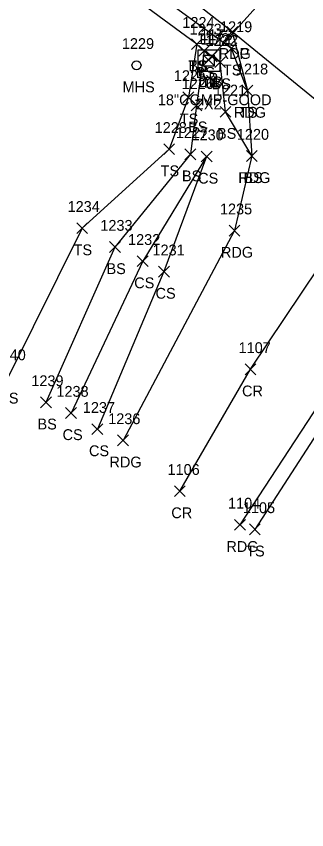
# Model space of a CAD drawing. Extents: x 1537342 to 1542195, y 163002 to 168596.
# Drawn here: x 1541938.8 to 1541992.5, y 163030.1 to 163180.4 of the extents above; entities that cross this region are included whole.
import ezdxf

# ---------------------------------------------------------------- set-up
doc = ezdxf.new("R2010")
doc.units = 0
for name, color, linetype in [('D_A', 7, 'Continuous'), ('D_C', 7, 'Continuous'), ('D_I', 7, 'Continuous'), ('D_TIC', 7, 'Continuous'), ('DCP', 7, 'Continuous'), ('DS', 7, 'Continuous'), ('L_A', 7, 'Continuous'), ('L_I', 7, 'Continuous'), ('L_TIC', 7, 'Continuous'), ('LELB', 7, 'Continuous'), ('P_A', 7, 'Continuous'), ('P_I', 7, 'Continuous'), ('P_TIC', 7, 'Continuous'), ('PET', 7, 'Continuous'), ('PEU', 7, 'Continuous'), ('PRC', 7, 'Continuous'), ('U_A', 7, 'Continuous'), ('U_I', 7, 'Continuous'), ('USMH', 7, 'Continuous')]:
    doc.layers.add(name, color=color, linetype=linetype)

msp = doc.modelspace()

# ---------------------------------------------------------------- linework, layer by layer
at = {"layer": 'D_TIC'}
for points in [[(1541973.36, 163171.23), (1541975.36, 163173.23)], [(1541975.36, 163171.23), (1541973.36, 163173.23)], [(1541973.93, 163171.92), (1541975.93, 163173.92)], [(1541975.93, 163171.92), (1541973.93, 163173.92)]]:
    msp.add_lwpolyline(points, dxfattribs=at)
at = {"layer": 'DCP'}
msp.add_lwpolyline([(1541974.93, 163172.92), (1542058.96, 163266.56)], dxfattribs=at)
at = {"layer": 'DS'}
for p, q in [((1541972.41, 163174.14), (1541976.41, 163174.14)), ((1541972.41, 163170.14), (1541972.41, 163174.14)), ((1541976.41, 163174.14), (1541976.41, 163170.14)), ((1541973.41, 163171.14), (1541973.41, 163173.14)), ((1541973.41, 163173.14), (1541975.41, 163173.14)), ((1541975.41, 163173.14), (1541975.41, 163171.14)), ((1541975.41, 163171.14), (1541973.41, 163171.14)), ((1541974.41, 163172.14), (1541974.41, 163172.14)), ((1541974.41, 163172.14), (1541974.41, 163172.14)), ((1541976.41, 163170.14), (1541972.41, 163170.14))]:
    msp.add_line(p, q, dxfattribs=at)
at = {"layer": 'L_TIC'}
for points in [[(1541971.19, 163174.21), (1541973.19, 163176.21)], [(1541973.19, 163174.21), (1541971.19, 163176.21)], [(1541971.19, 163174.21), (1541973.19, 163176.21)], [(1541973.19, 163174.21), (1541971.19, 163176.21)], [(1541972.52, 163172.98), (1541974.52, 163174.98)], [(1541974.52, 163172.98), (1541972.52, 163174.98)], [(1541972.52, 163172.98), (1541974.52, 163174.98)], [(1541974.52, 163172.98), (1541972.52, 163174.98)], [(1541977.59, 163173.42), (1541979.59, 163175.42)], [(1541979.59, 163173.42), (1541977.59, 163175.42)], [(1541975.49, 163170.88), (1541977.49, 163172.88)], [(1541977.49, 163170.88), (1541975.49, 163172.88)], [(1541980.52, 163165.61), (1541982.52, 163167.61)], [(1541982.52, 163165.61), (1541980.52, 163167.61)], [(1541969.62, 163164.38), (1541971.62, 163166.38)], [(1541971.62, 163164.38), (1541969.62, 163166.38)], [(1541971.12, 163162.91), (1541973.12, 163164.91)], [(1541973.12, 163162.91), (1541971.12, 163164.91)], [(1541976.46, 163161.71), (1541978.46, 163163.71)], [(1541978.46, 163161.71), (1541976.46, 163163.71)], [(1541966.08, 163154.79), (1541968.08, 163156.79)], [(1541968.08, 163154.79), (1541966.08, 163156.79)], [(1541969.99, 163153.86), (1541971.99, 163155.86)], [(1541971.99, 163153.86), (1541969.99, 163155.86)], [(1541972.98, 163153.44), (1541974.98, 163155.44)], [(1541974.98, 163153.44), (1541972.98, 163155.44)], [(1541972.98, 163153.44), (1541974.98, 163155.44)], [(1541974.98, 163153.44), (1541972.98, 163155.44)], [(1541981.35, 163153.54), (1541983.35, 163155.54)], [(1541983.35, 163153.54), (1541981.35, 163155.54)], [(1541950, 163140.2), (1541952, 163142.2)], [(1541952, 163140.2), (1541950, 163142.2)], [(1541956.05, 163136.72), (1541958.05, 163138.72)], [(1541958.05, 163136.72), (1541956.05, 163138.72)], [(1541961.17, 163134.1), (1541963.17, 163136.1)], [(1541963.17, 163134.1), (1541961.17, 163136.1)], [(1541965.11, 163132.17), (1541967.11, 163134.17)], [(1541967.11, 163132.17), (1541965.11, 163134.17)], [(1541943.3, 163108.01), (1541945.3, 163110.01)], [(1541945.3, 163108.01), (1541943.3, 163110.01)], [(1541947.93, 163106.05), (1541949.93, 163108.05)], [(1541949.93, 163106.05), (1541947.93, 163108.05)], [(1541952.8, 163103.07), (1541954.8, 163105.07)], [(1541954.8, 163103.07), (1541952.8, 163105.07)], [(1541981.89, 163084.55), (1541983.89, 163086.55)], [(1541983.89, 163084.55), (1541981.89, 163086.55)]]:
    msp.add_lwpolyline(points, dxfattribs=at)
at = {"layer": 'LELB'}
for points in [[(1541981.52, 163166.61), (1541978.59, 163174.42), (1541956.98, 163190.15), (1541924.16, 163215.18), (1541866.46, 163254), (1541852.65, 163260.98), (1541835.08, 163274.97), (1541811.52, 163294.95), (1541800.6, 163304.36), (1541792.57, 163308.98)], [(1541982.35, 163154.54), (1541977.46, 163162.71), (1541976.49, 163171.88), (1541973.52, 163173.98), (1541972.19, 163175.21), (1541955.89, 163187.24), (1541919.33, 163210.02), (1541893.74, 163229.08), (1541863.64, 163247.96), (1541848.89, 163252.66), (1541830.96, 163271.76), (1541807.53, 163290.35), (1541793.3, 163299.34), (1541792.63, 163303.62)], [(1541972.19, 163175.21), (1541970.62, 163165.38), (1541967.08, 163155.79), (1541951, 163141.2), (1541937.4, 163113.8)], [(1541973.52, 163173.98), (1541972.12, 163163.91), (1541970.99, 163154.86), (1541957.05, 163137.72), (1541944.3, 163109.01)], [(1541973.98, 163154.44), (1541962.17, 163135.1), (1541948.93, 163107.05)], [(1541973.98, 163154.44), (1541966.11, 163133.17), (1541953.8, 163104.07)], [(1542027.61, 163125.22), (1542015.77, 163124.56), (1542008.35, 163121.99), (1541997.1, 163107.53), (1541982.89, 163085.55)]]:
    msp.add_lwpolyline(points, dxfattribs=at)
at = {"layer": 'P_TIC'}
for points in [[(1541977.73, 163176.48), (1541979.73, 163178.48)], [(1541979.73, 163176.48), (1541977.73, 163178.48)], [(1541977.73, 163176.48), (1541979.73, 163178.48)], [(1541979.73, 163176.48), (1541977.73, 163178.48)], [(1541980.52, 163165.61), (1541982.52, 163167.61)], [(1541982.52, 163165.61), (1541980.52, 163167.61)], [(1541981.35, 163153.54), (1541983.35, 163155.54)], [(1541983.35, 163153.54), (1541981.35, 163155.54)], [(1541978.14, 163139.75), (1541980.14, 163141.75)], [(1541980.14, 163139.75), (1541978.14, 163141.75)], [(1541981.1, 163114.12), (1541983.1, 163116.12)], [(1541983.1, 163114.12), (1541981.1, 163116.12)], [(1541957.54, 163100.99), (1541959.54, 163102.99)], [(1541959.54, 163100.99), (1541957.54, 163102.99)], [(1541968.02, 163091.61), (1541970.02, 163093.61)], [(1541970.02, 163091.61), (1541968.02, 163093.61)], [(1541979.15, 163085.38), (1541981.15, 163087.38)], [(1541981.15, 163085.38), (1541979.15, 163087.38)]]:
    msp.add_lwpolyline(points, dxfattribs=at)
at = {"layer": 'PET'}
msp.add_lwpolyline([(1542165.56, 163030.05), (1542126.67, 163058.36), (1542096.32, 163082.47), (1542058.61, 163112.54), (1542052.02, 163117.84), (1542010.73, 163151.35), (1541978.73, 163177.48), (1541958.58, 163193.33), (1541928.58, 163217.89), (1541894.65, 163244.61), (1541857.53, 163271.04), (1541839.6, 163283.45), (1541795.58, 163311.16), (1541814.19, 163318.82), (1541832.22, 163326.69)], dxfattribs=at)
at = {"layer": 'PEU'}
for points in [[(1541978.73, 163177.48), (1541981.52, 163166.61), (1541982.35, 163154.54), (1541979.14, 163140.75), (1541958.54, 163101.99)], [(1542052.02, 163117.84), (1542027.61, 163125.22), (1542015.69, 163126.52), (1542006.7, 163123.23), (1541994.86, 163108.85), (1541980.15, 163086.38)]]:
    msp.add_lwpolyline(points, dxfattribs=at)
at = {"layer": 'PRC'}
msp.add_lwpolyline([(1541969.02, 163092.61), (1541982.1, 163115.12), (1541994.75, 163134.06), (1542010.73, 163151.35)], dxfattribs=at)
at = {"layer": 'USMH'}
for p, q in [((1541961.03, 163171.31), (1541961.03, 163171.31)), ((1541961.87, 163171.31), (1541961.87, 163171.31))]:
    msp.add_line(p, q, dxfattribs=at)
msp.add_circle((1541961.03, 163171.31), 0.833, dxfattribs=at)

# ---------------------------------------------------------------- texts
at = {"layer": 'D_A'}
for s, p in [('P', (1541974.3, 163167.92)), ('DIB', (1541972.46, 163167.23)), ('DI', (1541973.47, 163167.14))]:
    msp.add_text(s, height=2, dxfattribs=at).set_placement(p)
at = {"layer": 'D_C'}
for s, p in [('18"CGMP-GOOD', (1541964.97, 163163.92)), ('2X2', (1541971.99, 163163.14))]:
    msp.add_text(s, height=2, dxfattribs=at).set_placement(p)
at = {"layer": 'D_I'}
for s, p in [('1172', (1541972.23, 163175.23)), ('1173', (1541972.8, 163175.92)), ('1171', (1541972.85, 163175.14))]:
    msp.add_text(s, height=2, dxfattribs=at).set_placement(p)
at = {"layer": 'L_A'}
for s, p in [('TS', (1541970.6, 163170.21)), ('BS', (1541970.63, 163170.21)), ('BS', (1541971.96, 163168.98)), ('BS', (1541971.96, 163168.98)), ('TS', (1541977, 163169.42)), ('BS', (1541974.93, 163166.88)), ('TS', (1541979.93, 163161.61)), ('TS', (1541969.03, 163160.38)), ('BS', (1541970.56, 163158.91)), ('BS', (1541975.9, 163157.71)), ('TS', (1541965.49, 163150.79)), ('BS', (1541969.43, 163149.86)), ('CS', (1541972.42, 163149.44)), ('CS', (1541972.42, 163149.44)), ('BS', (1541980.79, 163149.54)), ('TS', (1541949.41, 163136.2)), ('BS', (1541955.49, 163132.72)), ('CS', (1541960.61, 163130.1)), ('CS', (1541964.55, 163128.17)), ('TS', (1541935.81, 163108.8)), ('BS', (1541942.74, 163104.01)), ('CS', (1541947.37, 163102.05)), ('CS', (1541952.25, 163099.07)), ('TS', (1541981.3, 163080.55))]:
    msp.add_text(s, height=2, dxfattribs=at).set_placement(p)
at = {"layer": 'L_I'}
for s, p in [('1224', (1541969.5, 163178.21)), ('1224', (1541969.5, 163178.21)), ('1223', (1541970.83, 163176.98)), ('1223', (1541970.83, 163176.98)), ('1219', (1541976.46, 163177.42)), ('1222', (1541973.8, 163174.88)), ('1218', (1541979.4, 163169.61)), ('1225', (1541967.93, 163168.38)), ('1226', (1541969.37, 163166.91)), ('1221', (1541975.33, 163165.71)), ('1228', (1541964.39, 163158.79)), ('1227', (1541968.3, 163157.86)), ('1230', (1541971.2, 163157.44)), ('1230', (1541971.2, 163157.44)), ('1220', (1541979.57, 163157.54)), ('1234', (1541948.3, 163144.2)), ('1233', (1541954.35, 163140.72)), ('1232', (1541959.47, 163138.1)), ('1231', (1541963.98, 163136.17)), ('1240', (1541934.62, 163116.8)), ('1239', (1541941.6, 163112.01)), ('1238', (1541946.23, 163110.05)), ('1237', (1541951.11, 163107.07)), ('1105', (1541980.68, 163088.55))]:
    msp.add_text(s, height=2, dxfattribs=at).set_placement(p)
at = {"layer": 'P_A'}
for s, p in [('RDG', (1541976.22, 163172.48)), ('RDP', (1541976.22, 163172.48)), ('RDG', (1541979.01, 163161.61)), ('RDG', (1541979.84, 163149.54)), ('RDG', (1541976.63, 163135.75)), ('CR', (1541980.53, 163110.12)), ('RDG', (1541956.03, 163096.99)), ('CR', (1541967.46, 163087.61)), ('RDG', (1541977.63, 163081.38))]:
    msp.add_text(s, height=2, dxfattribs=at).set_placement(p)
at = {"layer": 'P_I'}
for s, p in [('1218', (1541979.4, 163169.61)), ('1220', (1541979.57, 163157.54)), ('1235', (1541976.45, 163143.75)), ('1107', (1541979.89, 163118.12)), ('1236', (1541955.8, 163104.99)), ('1106', (1541966.76, 163095.61)), ('1104', (1541977.94, 163089.38))]:
    msp.add_text(s, height=2, dxfattribs=at).set_placement(p)
at = {"layer": 'U_A'}
msp.add_text('MHS', height=2, dxfattribs=at).set_placement((1541958.45, 163166.31))
at = {"layer": 'U_I'}
msp.add_text('1229', height=2, dxfattribs=at).set_placement((1541958.33, 163174.31))

doc.saveas('drawing.dxf')
